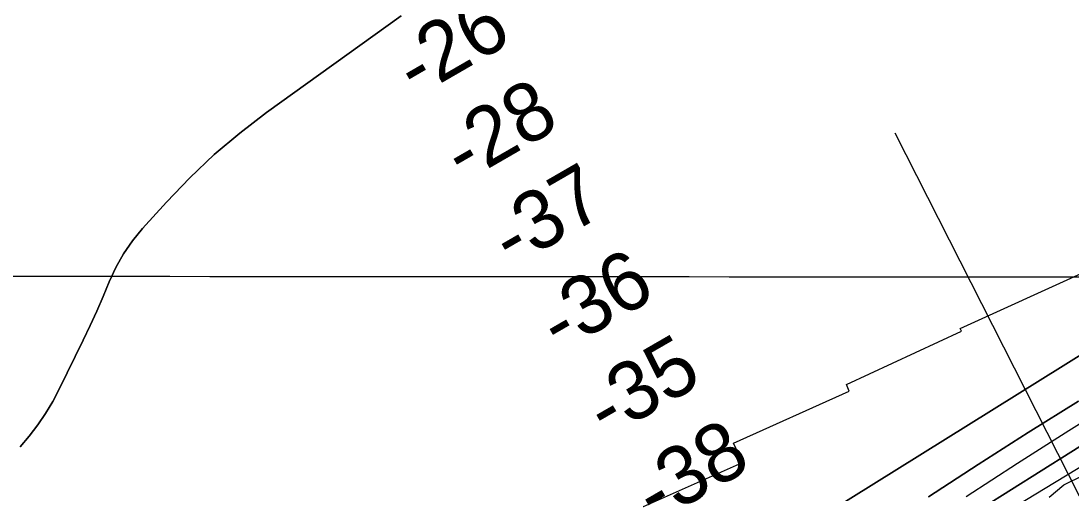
# Model space of a CAD drawing. Extents: x 3245246 to 3283090, y 806824 to 832173.
# Drawn here: x 3257079 to 3258154, y 818047 to 818531 of the extents above; entities that cross this region are included whole.
import ezdxf

# ---------------------------------------------------------------- set-up
doc = ezdxf.new("R2010")
doc.units = 0
for name, color, linetype in [('V-GRID-MAJR', 7, 'Continuous'), ('V-RIVR-EDGE', 7, 'Continuous'), ('V-RIVR-RANG', 7, 'Continuous'), ('V-RRAP-RVMT', 7, 'Continuous'), ('V-TOPO-DPTH', 7, 'Continuous'), ('V-TOPO-MINR', 7, 'Continuous')]:
    doc.layers.add(name, color=color, linetype=linetype)

msp = doc.modelspace()

# ---------------------------------------------------------------- linework, layer by layer
at = {"layer": 'V-GRID-MAJR'}
msp.add_spline([(3249418.2, 818275.5), (3254654, 818271.3), (3259889.9, 818267.9), (3265125.8, 818265.2), (3270361.6, 818263.3), (3275597.5, 818262.2), (3280833.3, 818261.8)], degree=3, dxfattribs=at)
at = {"layer": 'V-RIVR-EDGE'}
msp.add_lwpolyline([(3258131.4, 818043.6), (3258146.2, 818056.1), (3258185.9, 818075.6)], dxfattribs=at)
at = {"layer": 'V-RIVR-RANG'}
msp.add_line((3258508.5, 817364.3), (3257973.5, 818416.1), dxfattribs=at)
at = {"layer": 'V-RRAP-RVMT'}
for p, q in [((3258040.2, 818216.2), (3258168.3, 818274.6)), ((3258040.2, 818216.2), (3258168.3, 818274.6)), ((3257923.9, 818158.8), (3258041.4, 818213.4)), ((3257923.9, 818158.8), (3258041.4, 818213.4)), ((3258041.4, 818213.4), (3258040.2, 818216.2)), ((3258041.4, 818213.4), (3258040.2, 818216.2)), ((3257926.6, 818152.1), (3257923.9, 818158.8)), ((3257926.6, 818152.1), (3257923.9, 818158.8)), ((3257808, 818098.9), (3257926.6, 818152.1)), ((3257808, 818098.9), (3257926.6, 818152.1)), ((3257817.4, 818079), (3257808, 818098.9)), ((3257817.4, 818079), (3257808, 818098.9)), ((3257709.7, 818031.2), (3257817.4, 818079)), ((3257709.7, 818031.2), (3257817.4, 818079))]:
    msp.add_line(p, q, dxfattribs=at)
at = {"layer": 'V-TOPO-DPTH'}
for points in [[(3257467.7, 818536), (3257329.9, 818437.1), (3257302.6, 818416.1), (3257276.2, 818394), (3257251.3, 818370.3), (3257227.4, 818345.4), (3257202.9, 818318.3), (3257192.7, 818305.7), (3257183.4, 818292.6), (3257175.6, 818278.5), (3257168.8, 818263.9), (3257162.6, 818248.8), (3257156.1, 818233.9), (3257149.3, 818219.1), (3257142.3, 818204.3), (3257117.8, 818153.9), (3257111.1, 818141.3), (3257103.8, 818129.1), (3257095.7, 818117.4), (3257087, 818106.1), (3257077.7, 818095.2)], [(3257077.7, 818095.2), (3257087, 818106.1), (3257095.7, 818117.4), (3257103.8, 818129.1), (3257111.1, 818141.3), (3257117.8, 818153.9), (3257142.3, 818204.3), (3257149.3, 818219.1), (3257156.1, 818233.9), (3257162.6, 818248.8), (3257168.8, 818263.9), (3257175.6, 818278.5), (3257183.4, 818292.6), (3257192.7, 818305.7), (3257202.9, 818318.3), (3257227.4, 818345.4), (3257251.3, 818370.3), (3257276.2, 818394), (3257302.6, 818416.1), (3257329.9, 818437.1), (3257467.7, 818536)], [(3257901.8, 818026.2), (3258245.2, 818240)], [(3258245.2, 818240), (3257901.8, 818026.2)], [(3258007.6, 818043.9), (3258058.5, 818077.1), (3258109.9, 818109.7), (3258161.4, 818141.9)], [(3258161.4, 818141.9), (3258109.9, 818109.7), (3258058.5, 818077.1), (3258007.6, 818043.9)], [(3258183.9, 818108.7), (3257880.2, 817917.7)], [(3257880.2, 817917.7), (3258183.9, 818108.7)]]:
    msp.add_lwpolyline(points, dxfattribs=at)
at = {"layer": 'V-TOPO-MINR'}
for points in [[(3257467.7, 818536), (3257329.9, 818437.1), (3257302.6, 818416.1), (3257276.2, 818394), (3257251.3, 818370.3), (3257227.4, 818345.4), (3257202.9, 818318.3), (3257192.7, 818305.7), (3257183.4, 818292.6), (3257175.6, 818278.5), (3257168.8, 818263.9), (3257162.6, 818248.8), (3257156.1, 818233.9), (3257149.3, 818219.1), (3257142.3, 818204.3), (3257117.8, 818153.9), (3257111.1, 818141.3), (3257103.8, 818129.1), (3257095.7, 818117.4), (3257087, 818106.1), (3257077.7, 818095.2)], [(3257901.8, 818026.2), (3258245.2, 818240)], [(3258088.8, 818029.4), (3258127, 818052.6), (3258326.5, 818173.4)], [(3258046.4, 818044.4), (3258098.8, 818078.2), (3258151.4, 818111.8), (3258204.3, 818145)], [(3258007.6, 818043.9), (3258058.5, 818077.1), (3258109.9, 818109.7), (3258161.4, 818141.9)], [(3257880.2, 817917.7), (3258183.9, 818108.7)]]:
    msp.add_lwpolyline(points, dxfattribs=at)

# ---------------------------------------------------------------- texts
at = {"layer": 'V-RIVR-RANG'}
for s, p in [('-26', (3257483, 818452.2)), ('-28', (3257531.7, 818364.9)), ('-37', (3257580.9, 818277.8)), ('-36', (3257630, 818190.7)), ('-35', (3257677.9, 818102.9)), ('-38', (3257727.9, 818016.3))]:
    msp.add_text(s, height=60, rotation=30.0047, dxfattribs=at).set_placement(p)

doc.saveas('drawing.dxf')
